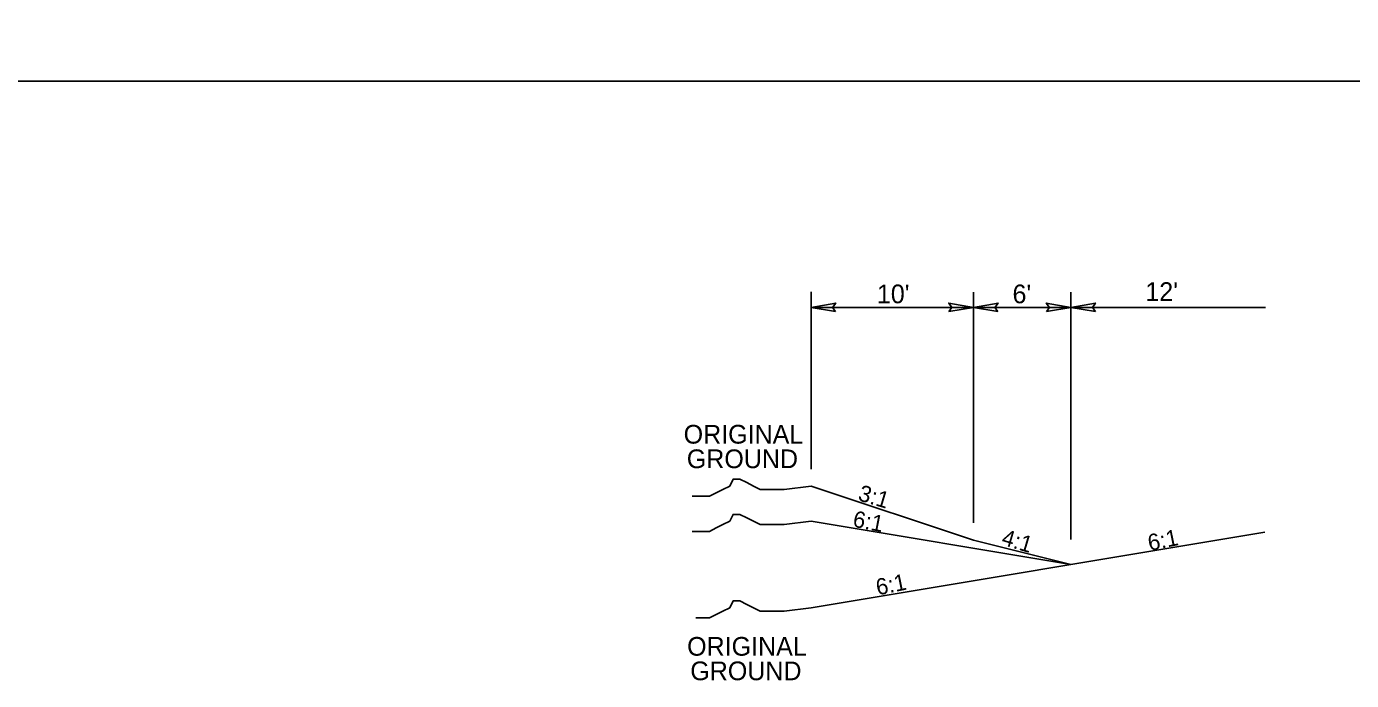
# Model space of a CAD drawing. Extents: x 2176024 to 2177225, y 75947 to 76635.
# Drawn here: x 2176725.6 to 2176807.2, y 76417.6 to 76457.9 of the extents above; entities that cross this region are included whole.
import ezdxf

# ---------------------------------------------------------------- set-up
doc = ezdxf.new("R2010")
doc.units = 0
for name, color, linetype in [('Prop Dimension', 7, 'Continuous'), ('Sheet Cutting Line CELL', 7, 'Continuous'), ('Sheet Plot Border Outside CELL', 7, 'Continuous'), ('Typical Pavement Slope CELL', 7, 'Continuous'), ('Typical Shoulder Slope CELL', 7, 'Continuous'), ('Typical Slope Point Local CELL', 7, 'Continuous'), ('Typical Terminator CELL', 7, 'Continuous'), ('Typical Text General CELL', 7, 'Continuous')]:
    doc.layers.add(name, color=color, linetype=linetype)

msp = doc.modelspace()

# ---------------------------------------------------------------- linework, layer by layer
at = {"layer": 'Prop Dimension'}
for p, q in [((2176773.911, 76430.569), (2176773.911, 76441.501)), ((2176783.911, 76427.267), (2176783.911, 76441.475)), ((2176789.911, 76426.249), (2176789.911, 76441.475)), ((2176783.911, 76440.548), (2176773.911, 76440.548)), ((2176789.911, 76440.548), (2176783.911, 76440.548)), ((2176801.911, 76440.548), (2176789.911, 76440.548))]:
    msp.add_line(p, q, dxfattribs=at)
at = {"layer": 'Sheet Cutting Line CELL'}
msp.add_line((2176629.267, 76454.475), (2176898.707, 76454.475), dxfattribs=at)
at = {"layer": 'Sheet Plot Border Outside CELL'}
msp.add_lwpolyline([(2176898.707, 76630.475), (2176629.267, 76630.475), (2176629.267, 76454.475), (2176898.707, 76454.475)], close=True, dxfattribs=at)
at = {"layer": 'Typical Pavement Slope CELL'}
for p, q in [((2176789.911, 76424.705), (2176773.911, 76427.371)), ((2176773.911, 76422.038), (2176801.863, 76426.697))]:
    msp.add_line(p, q, dxfattribs=at)
at = {"layer": 'Typical Shoulder Slope CELL'}
for p, q in [((2176783.911, 76426.205), (2176773.911, 76429.538)), ((2176789.911, 76424.705), (2176783.911, 76426.205))]:
    msp.add_line(p, q, dxfattribs=at)
at = {"layer": 'Typical Slope Point Local CELL'}
for points in [[(2176773.911, 76429.538), (2176772.24, 76429.33), (2176771.822, 76429.33), (2176771.195, 76429.33), (2176770.778, 76429.33), (2176770.36, 76429.538), (2176769.942, 76429.748), (2176769.525, 76429.957), (2176769.107, 76429.957), (2176768.897, 76429.538), (2176768.48, 76429.33), (2176768.062, 76429.12), (2176767.644, 76428.912), (2176767.227, 76428.912), (2176766.809, 76428.912), (2176766.577, 76428.912)], [(2176773.911, 76427.371), (2176772.24, 76427.163), (2176771.822, 76427.163), (2176771.195, 76427.163), (2176770.777, 76427.163), (2176770.36, 76427.371), (2176769.942, 76427.581), (2176769.524, 76427.791), (2176769.107, 76427.791), (2176768.897, 76427.371), (2176768.479, 76427.163), (2176768.062, 76426.954), (2176767.644, 76426.746), (2176767.226, 76426.746), (2176766.809, 76426.746), (2176766.577, 76426.746)], [(2176773.911, 76422.038), (2176772.24, 76421.83), (2176771.822, 76421.83), (2176771.195, 76421.83), (2176770.778, 76421.83), (2176770.36, 76422.038), (2176769.942, 76422.248), (2176769.525, 76422.457), (2176769.107, 76422.457), (2176768.897, 76422.038), (2176768.48, 76421.83), (2176768.062, 76421.62), (2176767.644, 76421.412), (2176767.227, 76421.412), (2176766.809, 76421.412), (2176766.798, 76421.412)]]:
    msp.add_lwpolyline(points, dxfattribs=at)
at = {"layer": 'Typical Terminator CELL'}
for points in [[(2176775.42, 76440.288), (2176773.911, 76440.548), (2176775.429, 76440.816), (2176775.236, 76440.548)], [(2176782.401, 76440.288), (2176783.911, 76440.548), (2176782.393, 76440.816), (2176782.586, 76440.548)], [(2176785.42, 76440.288), (2176783.911, 76440.548), (2176785.429, 76440.816), (2176785.236, 76440.548)], [(2176788.401, 76440.288), (2176789.911, 76440.548), (2176788.393, 76440.816), (2176788.586, 76440.548)], [(2176791.42, 76440.288), (2176789.911, 76440.548), (2176791.429, 76440.816), (2176791.236, 76440.548)]]:
    msp.add_lwpolyline(points, close=True, dxfattribs=at)

# ---------------------------------------------------------------- texts
at = {"layer": 'Typical Slope Point Local CELL'}
for s, rotation, p in [('3:1', 343.53506, (2176776.746, 76428.671)), ('6:1', 349.18318, (2176776.427, 76427.043)), ('6:1', 11.48655, (2176794.763, 76425.535)), ('4:1', 343.53506, (2176785.578, 76425.938)), ('6:1', 11.48655, (2176778.013, 76422.794))]:
    msp.add_text(s, height=1.0064, rotation=rotation, dxfattribs=at).set_placement(p)
at = {"layer": 'Typical Text General CELL'}
for s, p in [("10'", (2176777.963, 76440.8)), ("6'", (2176786.317, 76440.8)), ("12' ", (2176794.501, 76440.943)), ('ORIGINAL', (2176766.057, 76432.152)), ('GROUND', (2176766.251, 76430.64)), ('ORIGINAL', (2176766.271, 76419.083)), ('GROUND', (2176766.465, 76417.571))]:
    msp.add_text(s, height=1.1533, dxfattribs=at).set_placement(p)

doc.saveas('drawing.dxf')
